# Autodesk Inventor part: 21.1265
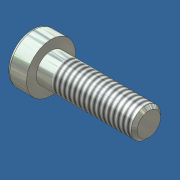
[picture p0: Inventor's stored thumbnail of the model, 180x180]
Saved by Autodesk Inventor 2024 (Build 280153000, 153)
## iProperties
Created: 2006-02
Part Number: 21.1265
Material: Steel, Mild
Description: M6X22 SHCS
Document SubType Name: Modeling
Standard: DIN 7984
Designer: Andy Moles
Standards Organization: DIN
Language: en-US
Size Designation: M6 x 20
Categories: <MemberInstance><Categories><Category DisplayName="Fasteners" InternalName="e4da775c-781d-43d5-af7c-5136215cf5a6" Mnemonic="FSTN"><Category DisplayName="Bolts"
Density: 7.85 g/cm^3
Mass: 6.92147 g
Surface Area: 7.27259 cm^2
Volume: 0.881716 cm^3
Appearance: Zinc
Title: 21.1265 M6X22 SHCS LOW HEAD ZINC PLATED
Author: Andy Moles
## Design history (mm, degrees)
workplane "Work Plane1"
revolve "Body" stored, may be unused: angle "d10" = 90 deg
sketch "Sketch2"
  geometry: L1 (0, -6)-(0, 8) reference; L2 (-6, 0)-(8, 0) reference; L3 (2.309, 0)-(1.155, -2); L4 (1.155, -2)-(-1.155, -2); L5 (-1.155, -2)-(-2.309, 0); L6 (-2.309, 0)-(-1.155, 2); L7 (-1.155, 2)-(1.155, 2); L8 (1.155, 2)-(2.309, 0); 2 further points
  constraints: 12 end point, 1 coincident, 1 horizontal alignment, 1 point on line, 12 other
extrude "Slot" join sketch "Sketch2" stored distance "d11" = 10; taper "d12" = 0 deg
body "Solid1"
fillet "Fillet1" dims "d17" = 0.6 (= RR)
feature "Thread" dims "d13" = 22, "d14" = 0
chamfer "Chamfer1" distance "d15" = 0.61345 (= -0.5 x SPD + 0.5 x GD); stored, may be unused: second distance "d16" = 0.61345 (= GUL), angle "d27" = 45 deg
sketch "Sketch1"
  geometry: L1 (0.333, 0)-(22, 0); L2 (22, 0)-(22, 3); L3 (22, 3)-(3, 3); L4 (3, 3)-(2.386, 3); L5 (2.386, 3)-(0, 3); L6 (0, 3)-(0, 5); L7 (0, 5)-(-4, 5); L8 (-4, 5)-(-4, 2.309); L9 (-4, 2.309)-(-1, 2.309); L10 (-1, 2.309)-(0.333, 0); L11 (-6.4, 0)-(27.2, 0) reference; L12 (0, -0.5)-(0, 6.5) reference; L13 (3, 3)-(0, 3)
  constraints: 22 end point, 6 parallel, 2 collinear, 2 perpendicular, 1 horizontal, 1 midpoint
  dimensions: "d1" = 19 distance from line of L3.end L2 (= GEL); "d2" = 0.61355 distance of L4.end L3.end (computed from GAL); "d3" = 4 distance between parallel lines of L8 L6 (= KOH); "d4" = 3 distance of L8.end L9.end (= INTI); "d5" = 60 deg angle of L10 L1; "d6" = 6 diameter of L3 L1 (= GD); "d7" = 6 diameter of L5 L1 (= BDM); "d8" = 4.6188 diameter of L9 L1 (= 1.1547 x SW); "d9" = 10 diameter of L7 L1 (= KOD); "d26" = 22 distance between parallel lines of L12 L2 (= NLG)
other parameters: "GD" = 6 (= NND) [user parameter; used in 2 equation terms], "NLG" = 22 [user parameter; used in 1 equation term], "GEL" = 19 [user parameter; used in 1 equation term], "KOD" = 10 [user parameter; used in 1 equation term], "KOH" = 4 [user parameter; used in 1 equation term], "INTI" = 3 [user parameter; used in 1 equation term], "GAL" = 0.61345 (= 0.61345 x PTC) [user parameter; used in 1 equation term], "GUL" = 0.61345 (= 0.61345 x PTC) [user parameter; used in 1 equation term], "BDM" = 6 (= NND) [user parameter; used in 1 equation term], "SW" = 4 [user parameter; used in 2 equation terms], "RR" = 0.6 [user parameter; used in 1 equation term], "SPD" = 4.7731 (= NND - 1.2269 x PTC) [user parameter; used in 1 equation term], "d19" = 0, "d28" = 0, "d29" = 0, "TOA" = 30 deg [user parameter], "GD1" = 4.7731 (= THREADDIA - 1.2269 x PTC) [user parameter], "THREADDIA" = 6 [user parameter; used in 1 equation term], "FAWI" = 45 deg [user parameter], "ANG" = 120 deg [user parameter], "PTC" = 1 [user parameter; used in 5 equation terms], "NND" = 6 [user parameter; used in 3 equation terms], "E0" = 4.62 (= 1.155 x SW) [user parameter]
